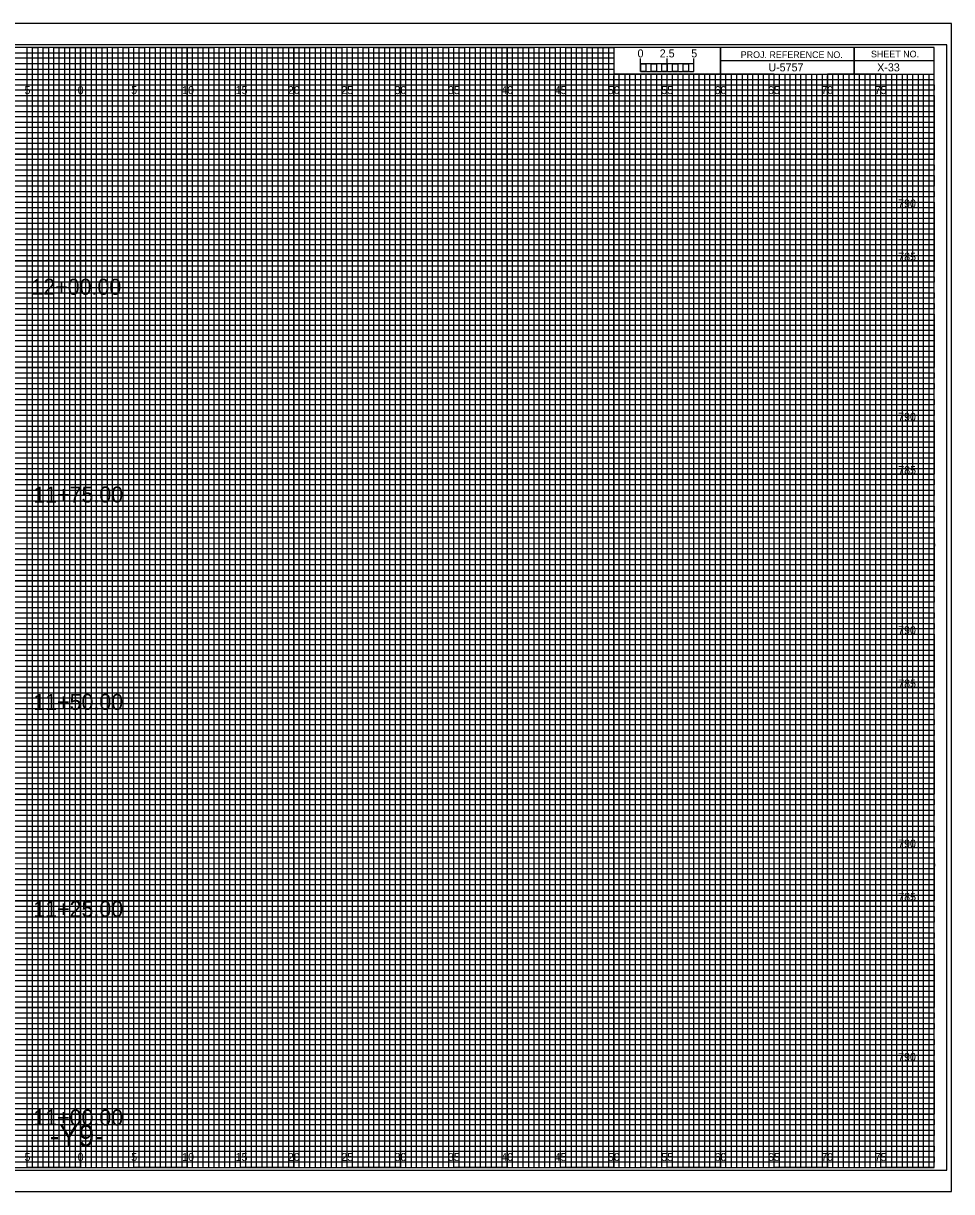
# Model space of a CAD drawing. Extents: x -7 to 162, y 108 to 217.
# Drawn here: x 74.6 to 161.7, y 107.7 to 217.2 of the extents above; entities that cross this region are included whole.
import ezdxf

# ---------------------------------------------------------------- set-up
doc = ezdxf.new("R2010")
doc.units = 0
for name, color, linetype in [('Exist Cross Section Cell', 7, 'Continuous'), ('Exist XS Center Line Elevation Label', 7, 'Continuous'), ('Prop CMT Pvmt Course 2 Wedge', 7, 'Continuous'), ('Prop CMT Pvmt Surface Shoulder', 7, 'Continuous'), ('Prop CMT Shld Paved Course 1', 7, 'Continuous'), ('Prop CMT Shld Paved Course 2', 7, 'Continuous'), ('Prop CMT Shld Paved Course 3', 7, 'Continuous'), ('Prop XS Alignment Label', 7, 'Continuous'), ('Prop XS Bar Scale Labels', 7, 'Continuous'), ('Prop XS Elevation Labels', 7, 'Continuous'), ('Prop XS Hydro Elevations', 7, 'Continuous'), ('Prop XS Project Number', 7, 'Continuous'), ('Prop XS SE Text', 7, 'Continuous'), ('Prop XS Sheet Number', 7, 'Continuous'), ('Prop XS Side Slope Text', 7, 'Continuous'), ('Prop XS Station Labels', 7, 'Continuous'), ('Sheet Cutting Line CELL', 7, 'Continuous')]:
    doc.layers.add(name, color=color, linetype=linetype)

msp = doc.modelspace()

# ---------------------------------------------------------------- linework, layer by layer
at = {"layer": 'Exist Cross Section Cell'}
for p, q in [((75, 215), (70, 215)), ((75, 110), (75, 215)), ((85, 215), (80, 215)), ((80, 215), (80, 110)), ((85, 110), (85, 215)), ((95, 215), (90, 215)), ((90, 215), (90, 110)), ((95, 110), (95, 215)), ((105, 215), (100, 215)), ((100, 215), (100, 110)), ((105, 110), (105, 215)), ((115, 215), (110, 215)), ((110, 215), (110, 110)), ((115, 110), (115, 215)), ((125, 215), (120, 215)), ((120, 215), (120, 110)), ((125, 110), (125, 215)), ((130, 215), (130, 110)), ((135, 110), (135, 212.5)), ((145, 212.5), (140, 212.5)), ((140, 212.5), (140, 110)), ((145, 110), (145, 212.5)), ((155, 212.5), (150, 212.5)), ((150, 212.5), (150, 110)), ((155, 110), (155, 212.5)), ((80, 110), (75, 110)), ((90, 110), (85, 110)), ((100, 110), (95, 110)), ((110, 110), (105, 110)), ((120, 110), (115, 110)), ((130, 110), (125, 110)), ((140, 110), (135, 110)), ((150, 110), (145, 110)), ((160, 110), (155, 110)), ((160, 110), (160, 110))]:
    msp.add_line(p, q, dxfattribs=at)
for points in [[(0, 210), (160, 210), (160, 205), (0, 205)], [(0, 200), (160, 200), (160, 195), (0, 195)], [(0, 190), (160, 190), (160, 185), (0, 185)], [(0, 180), (160, 180), (160, 175), (0, 175)], [(0, 170), (160, 170), (160, 165), (0, 165)], [(0, 160), (160, 160), (160, 155), (0, 155)], [(0, 150), (160, 150), (160, 145), (0, 145)], [(0, 140), (160, 140), (160, 135), (0, 135)], [(0, 130), (160, 130), (160, 125), (0, 125)], [(0, 120), (160, 120), (160, 115), (0, 115)]]:
    msp.add_lwpolyline(points, dxfattribs=at)
at = {"layer": 'Exist XS Center Line Elevation Label'}
for points in [[(72.5, 110), (77.5, 110), (77.5, 215), (82.5, 215), (82.5, 110), (87.5, 110), (87.5, 215), (92.5, 215), (92.5, 110), (97.5, 110), (97.5, 215), (102.5, 215), (102.5, 110), (107.5, 110), (107.5, 215), (112.5, 215), (112.5, 110), (117.5, 110), (117.5, 215), (122.5, 215), (122.5, 110), (127.5, 110), (127.5, 215), (129.97, 215), (130, 215), (130, 212.5), (132.5, 212.5), (132.5, 110), (137.5, 110), (137.5, 212.5), (142.5, 212.5), (142.5, 110), (147.5, 110), (147.5, 212.5), (152.5, 212.5), (152.5, 110), (157.5, 110), (157.5, 212.5)], [(0, 212.5), (137.5, 212.5)], [(0, 202.5), (160, 202.5), (160, 207.5), (0, 207.5)], [(0, 192.5), (160, 192.5), (160, 197.5), (0, 197.5)], [(0, 182.5), (160, 182.5), (160, 187.5), (0, 187.5)], [(0, 172.5), (160, 172.5), (160, 177.5), (0, 177.5)], [(0, 162.5), (160, 162.5), (160, 167.5), (0, 167.5)], [(0, 152.5), (160, 152.5), (160, 157.5), (0, 157.5)], [(0, 142.5), (160, 142.5), (160, 147.5), (0, 147.5)], [(0, 132.5), (160, 132.5), (160, 137.5), (0, 137.5)], [(0, 122.5), (160, 122.5), (160, 127.5), (0, 127.5)], [(0, 112.5), (160, 112.5), (160, 117.5), (0, 117.5)]]:
    msp.add_lwpolyline(points, dxfattribs=at)
at = {"layer": 'Prop CMT Pvmt Course 2 Wedge'}
for p, q in [((75, 110), (75, 215)), ((80, 110), (80, 215)), ((85, 110), (85, 215)), ((90, 110), (90, 215)), ((95, 110), (95, 215)), ((100, 110), (100, 215)), ((105, 110), (105, 215)), ((110, 110), (110, 215)), ((115, 110), (115, 215)), ((120, 110), (120, 215)), ((125, 110), (125, 215)), ((130, 110), (130, 212.34)), ((135, 110), (135, 212.34)), ((140, 110), (140, 212.34)), ((145, 110), (145, 212.34)), ((150, 110), (150, 212.34)), ((155, 110), (155, 212.34)), ((0, 210), (160, 210)), ((0, 205), (160, 205)), ((0, 200), (160, 200)), ((0, 195), (160, 195)), ((0, 190), (160, 190)), ((0, 185), (160, 185)), ((0, 180), (160, 180)), ((0, 175), (160, 175)), ((0, 170), (160, 170)), ((0, 165), (160, 165)), ((0, 160), (160, 160)), ((0, 155), (160, 155)), ((0, 150), (160, 150)), ((0, 145), (160, 145)), ((0, 140), (160, 140)), ((0, 135), (160, 135)), ((0, 130), (160, 130)), ((0, 125), (160, 125)), ((0, 120), (160, 120)), ((0, 115), (160, 115))]:
    msp.add_line(p, q, dxfattribs=at)
at = {"layer": 'Prop CMT Pvmt Surface Shoulder'}
msp.add_lwpolyline([(-5.4, 109.75), (161.2, 109.75), (161.2, 215.25), (-5.4, 215.25)], close=True, dxfattribs=at)
at = {"layer": 'Prop CMT Shld Paved Course 1'}
for p, q in [((133.5, 212.5), (133, 212.5)), ((133, 212.5), (133, 110)), ((133.5, 110), (133.5, 212.5)), ((134.5, 212.5), (134, 212.5)), ((134, 212.5), (134, 110)), ((134.5, 110), (134.5, 212.5)), ((133, 110), (132.5, 110)), ((134, 110), (133.5, 110))]:
    msp.add_line(p, q, dxfattribs=at)
for points in [[(75, 110), (75.5, 110), (75.5, 215), (76, 215), (76, 110)], [(76, 110), (76.5, 110), (76.5, 215), (77, 215), (77, 110)], [(77.5, 110), (78, 110), (78, 215), (78.5, 215), (78.5, 110)], [(78.5, 110), (79, 110), (79, 215), (79.5, 215), (79.5, 110)], [(80, 110), (80.5, 110), (80.5, 215), (81, 215), (81, 110)], [(81, 110), (81.5, 110), (81.5, 215), (82, 215), (82, 110)], [(82.5, 110), (83, 110), (83, 215), (83.5, 215), (83.5, 110)], [(83.5, 110), (84, 110), (84, 215), (84.5, 215), (84.5, 110)], [(85, 110), (85.5, 110), (85.5, 215), (86, 215), (86, 110)], [(86, 110), (86.5, 110), (86.5, 215), (87, 215), (87, 110)], [(87.5, 110), (88, 110), (88, 215), (88.5, 215), (88.5, 110)], [(88.5, 110), (89, 110), (89, 215), (89.5, 215), (89.5, 110)], [(90, 110), (90.5, 110), (90.5, 215), (91, 215), (91, 110)], [(91, 110), (91.5, 110), (91.5, 215), (92, 215), (92, 110)], [(92.5, 110), (93, 110), (93, 215), (93.5, 215), (93.5, 110)], [(93.5, 110), (94, 110), (94, 215), (94.5, 215), (94.5, 110)], [(95, 110), (95.5, 110), (95.5, 215), (96, 215), (96, 110)], [(96, 110), (96.5, 110), (96.5, 215), (97, 215), (97, 110)], [(97.5, 110), (98, 110), (98, 215), (98.5, 215), (98.5, 110)], [(98.5, 110), (99, 110), (99, 215), (99.5, 215), (99.5, 110)], [(100, 110), (100.5, 110), (100.5, 215), (101, 215), (101, 110)], [(101, 110), (101.5, 110), (101.5, 215), (102, 215), (102, 110)], [(102.5, 110), (103, 110), (103, 215), (103.5, 215), (103.5, 110)], [(103.5, 110), (104, 110), (104, 215), (104.5, 215), (104.5, 110)], [(105, 110), (105.5, 110), (105.5, 215), (106, 215), (106, 110)], [(106, 110), (106.5, 110), (106.5, 215), (107, 215), (107, 110)], [(107.5, 110), (108, 110), (108, 215), (108.5, 215), (108.5, 110)], [(108.5, 110), (109, 110), (109, 215), (109.5, 215), (109.5, 110)], [(110, 110), (110.5, 110), (110.5, 215), (111, 215), (111, 110)], [(111, 110), (111.5, 110), (111.5, 215), (112, 215), (112, 110)], [(112.5, 110), (113, 110), (113, 215), (113.5, 215), (113.5, 110)], [(113.5, 110), (114, 110), (114, 215), (114.5, 215), (114.5, 110)], [(115, 110), (115.5, 110), (115.5, 215), (116, 215), (116, 110)], [(116, 110), (116.5, 110), (116.5, 215), (117, 215), (117, 110)], [(117.5, 110), (118, 110), (118, 215), (118.5, 215), (118.5, 110)], [(118.5, 110), (119, 110), (119, 215), (119.5, 215), (119.5, 110)], [(120, 110), (120.5, 110), (120.5, 215), (121, 215), (121, 110)], [(121, 110), (121.5, 110), (121.5, 215), (122, 215), (122, 110)], [(122.5, 110), (123, 110), (123, 215), (123.5, 215), (123.5, 110)], [(123.5, 110), (124, 110), (124, 215), (124.5, 215), (124.5, 110)], [(125, 110), (125.5, 110), (125.5, 215), (126, 215), (126, 110)], [(126, 110), (126.5, 110), (126.5, 215), (127, 215), (127, 110)], [(127.5, 110), (128, 110), (128, 215), (128.5, 215), (128.5, 110)], [(128.5, 110), (129, 110), (129, 215), (129.5, 215), (129.5, 110)], [(130, 110), (130.5, 110), (130.5, 212.5), (131.01, 212.5), (131.01, 110)], [(131, 110), (131.5, 110), (131.5, 212.5), (132, 212.5), (132, 110)], [(135, 110), (135.49, 110), (135.49, 212.5), (136, 212.5), (136, 110)], [(136, 110), (136.5, 110), (136.5, 212.5), (137.03, 212.5), (137.03, 110)], [(137.5, 110), (138, 110), (138, 212.5), (138.5, 212.5), (138.5, 110)], [(138.5, 110), (139, 110), (139, 212.5), (139.5, 212.5), (139.5, 110)], [(140, 110), (140.5, 110), (140.5, 212.5), (141, 212.5), (141, 110)], [(141, 110), (141.5, 110), (141.5, 212.5), (142, 212.5), (142, 110)], [(142.5, 110), (143, 110), (143, 212.5), (143.5, 212.5), (143.5, 110)], [(143.5, 110), (144, 110), (144, 212.5), (144.5, 212.5), (144.5, 110)], [(145, 110), (145.5, 110), (145.5, 212.5), (146, 212.5), (146, 110)], [(146, 110), (146.5, 110), (146.5, 212.5), (147, 212.5), (147, 110)], [(147.5, 110), (148, 110), (148, 212.5), (148.5, 212.5), (148.5, 110)], [(148.5, 110), (149, 110), (149, 212.5), (149.5, 212.5), (149.5, 110)], [(150, 110), (150.5, 110), (150.5, 212.5), (151, 212.5), (151, 110)], [(151, 110), (151.5, 110), (151.5, 212.5), (152, 212.5), (152, 110)], [(152.5, 110), (153, 110), (153, 212.5), (153.5, 212.5), (153.5, 110)], [(153.5, 110), (154, 110), (154, 212.5), (154.5, 212.5), (154.5, 110)], [(155, 110), (155.5, 110), (155.5, 212.5), (156, 212.5), (156, 110)], [(156, 110), (156.5, 110), (156.5, 212.5), (157, 212.5), (157, 110)], [(157.5, 110), (158, 110), (158, 212.5), (158.5, 212.5), (158.5, 110)], [(158.5, 110), (159, 110), (159, 212.5), (159.5, 212.5), (159.5, 110)]]:
    msp.add_lwpolyline(points, dxfattribs=at)
at = {"layer": 'Prop CMT Shld Paved Course 2'}
for p, q in [((132.5, 212.75), (132.5, 213.95)), ((132.5, 213.45), (132.5, 213.95)), ((135, 212.75), (135, 213.95)), ((137.5, 212.75), (137.5, 213.95)), ((137.5, 213.45), (137.5, 213.95))]:
    msp.add_line(p, q, dxfattribs=at)
for points in [[(137.5, 213.45), (132.5, 213.45), (132.5, 212.75), (137.5, 212.75)], [(132.5, 213.45), (133, 213.45), (133, 212.75), (132.5, 212.75)], [(133.5, 213.45), (134, 213.45), (134, 212.75), (133.5, 212.75)], [(134.5, 213.45), (135, 213.45), (135, 212.75), (134.5, 212.75)], [(135.5, 213.45), (136, 213.45), (136, 212.75), (135.5, 212.75)], [(136.5, 213.45), (137, 213.45), (137, 212.75), (136.5, 212.75)]]:
    msp.add_lwpolyline(points, close=True, dxfattribs=at)
at = {"layer": 'Prop CMT Shld Paved Course 3'}
msp.add_lwpolyline([(-6.7, 107.75), (161.65, 107.75), (161.65, 217.25), (-6.7, 217.25)], close=True, dxfattribs=at)
at = {"layer": 'Prop XS Hydro Elevations'}
for p, q in [((152.5, 215), (152.5, 212.5)), ((152.5, 212.5), (152.5, 215)), ((160, 213.75), (140, 213.75)), ((140, 213.75), (140, 212.5)), ((140, 212.5), (160, 212.5))]:
    msp.add_line(p, q, dxfattribs=at)
for points in [[(160, 215), (0, 215), (0, 110), (160, 110)], [(140, 215), (130, 215), (130, 212.52), (140, 212.52)], [(160, 215), (140, 215), (140, 212.5), (160, 212.5)]]:
    msp.add_lwpolyline(points, close=True, dxfattribs=at)
at = {"layer": 'Prop XS Side Slope Text'}
for p, q in [((0, 214.5), (130, 214.5)), ((130, 213.99), (0, 213.99)), ((130, 214.5), (130, 213.99)), ((0, 213.5), (130, 213.5)), ((130, 212.94), (0, 212.94)), ((130, 213.5), (130, 212.94)), ((0, 212), (160, 212))]:
    msp.add_line(p, q, dxfattribs=at)
for points in [[(0, 211.5), (135, 211.5), (160, 211.5), (160, 211), (0, 211)], [(0, 210.5), (160, 210.5), (160, 209.5), (0, 209.5)], [(0, 209), (160, 209), (160, 208.5), (0, 208.49)], [(0, 208), (160, 208), (160, 207), (0, 207)], [(0, 206.5), (160, 206.5), (160, 206), (0, 206)], [(0, 205.5), (160, 205.5), (160, 204.5), (0, 204.5)], [(0, 204), (160, 204), (160, 203.5), (0, 203.5)], [(0, 203), (160, 203), (160, 202), (0, 202)], [(0, 201.5), (160, 201.5), (160, 201), (0, 201)], [(0, 200.5), (160, 200.5), (160, 199.5), (0, 199.5)], [(0, 199), (160, 199), (160, 198.5), (0, 198.5)], [(0, 198), (160, 198), (160, 196.97), (160, 196.5), (160, 196), (0, 196)], [(0, 197), (160, 197), (160, 196.5), (0, 196.5)], [(0, 195.5), (160, 195.5), (160, 194.5), (0, 194.52)], [(0, 194.52), (160, 194.5), (160, 194), (0, 194)], [(0, 193.5), (160, 193.5), (160, 193), (0, 193)], [(0, 192), (160, 192), (160, 191.5), (0, 191.5)], [(0, 191), (160, 191), (160, 190.5), (0, 190.5)], [(-0.04, 189.44), (160, 189.44), (160, 188.94), (-0.04, 188.94)], [(0, 188.5), (160, 188.5), (160, 188), (0, 188)], [(0, 187), (160, 187), (160, 186.5), (0, 186.5)], [(0, 186), (160, 186), (160, 185.5), (0, 185.5)], [(0, 184.5), (160, 184.5), (160, 184), (0, 184)], [(0, 183.5), (160, 183.5), (160, 183), (0, 183)], [(0, 182), (160, 182), (160, 181.5), (0, 181.5)], [(0, 181), (160, 181), (160, 180.5), (0, 180.5)], [(0, 179.5), (160, 179.5), (160, 178.99), (0, 179)], [(0, 178.5), (160, 178.5), (160, 178), (0, 178)], [(0, 177), (160, 177), (160, 176.5), (0, 176.5)], [(0, 176), (160, 176), (160, 175.5), (0, 175.5)], [(0, 174.5), (160, 174.5), (160, 174), (0, 174)], [(0, 173.5), (160, 173.5), (160, 173), (0, 173)], [(0, 172), (160, 172), (160, 171.5), (0, 171.5)], [(0, 171), (160, 171), (160, 170.5), (0, 170.5)], [(0, 169.5), (160, 169.5), (160, 169), (0, 169)], [(0, 168.5), (160.03, 168.46), (160, 168), (0, 168)], [(0, 167), (160, 167), (160, 166.5), (0, 166.5)], [(0, 166), (160, 166), (160, 165.5), (0, 165.5)], [(0, 164.5), (160, 164.5), (160, 164), (0, 164)], [(0, 163.5), (160, 163.5), (160, 163), (0, 163)], [(0, 162), (160, 162), (160, 161.5), (0, 161.5)], [(0, 161), (160, 161), (160, 160.5), (0, 160.5)], [(0, 159.5), (160, 159.5), (160, 159), (0, 159)], [(0, 158.5), (160, 158.5), (160, 158), (0, 158)], [(0, 157), (160, 157), (160, 156.5), (0, 156.5)], [(0, 156), (160, 156), (160, 155.5), (0, 155.5)], [(0, 154.5), (160, 154.5), (160, 154), (0, 154)], [(0, 153.5), (160, 153.5), (160, 153), (0, 153)], [(0, 152), (160, 152), (160, 151.5), (0, 151.5)], [(0, 151), (160, 151), (160, 150.5), (0, 150.5)], [(0, 149.5), (160, 149.5), (160, 148.99), (0, 149)], [(0, 148.5), (160, 148.5), (160, 148), (0, 148)], [(0, 147), (160, 147), (160, 146.5), (0, 146.5)], [(0, 146), (160, 146), (160, 145.5), (0, 145.5)], [(0, 144.5), (160, 144.5), (160, 144), (0, 144)], [(0, 143.5), (160, 143.5), (160, 143), (0, 143)], [(0, 142), (160, 142), (160, 141.5), (0, 141.5)], [(0, 141), (160, 141), (160, 140.5), (0, 140.5)], [(0, 139.5), (160, 139.5), (160, 139), (0, 139)], [(0, 138.5), (160.03, 138.46), (160, 138), (0, 138)], [(0, 137), (160, 137), (160, 136.5), (0, 136.5)], [(0, 136), (160, 136), (160, 135.5), (0, 135.5)], [(0, 134.5), (160, 134.5), (160, 134), (0, 134)], [(0, 133.5), (160, 133.5), (160, 133), (0, 133)], [(0, 132), (160, 132), (160, 131.5), (0, 131.5)], [(0, 131), (160, 131), (160, 130.5), (0, 130.5)], [(0, 129.5), (160, 129.5), (160, 129), (0, 129)], [(0, 128.5), (160, 128.5), (160, 128), (0, 128)], [(0, 127), (160, 127), (160, 126.5), (0, 126.5)], [(0, 126), (160, 126), (160, 125.5), (0, 125.5)], [(0, 124.5), (160, 124.5), (160, 124), (0, 124)], [(0, 123.5), (160, 123.5), (160, 123), (0, 123)], [(0, 122), (160, 122), (160, 121.5), (0, 121.5)], [(0, 121), (160, 121), (160, 120.5), (0, 120.5)], [(0, 119.5), (160, 119.5), (160, 119), (0, 119)], [(0, 118.5), (160, 118.5), (160, 118), (0, 118)], [(0, 117), (160, 117), (160, 116.5), (0, 116.5)], [(0, 116), (160, 116), (160, 115.5), (0, 115.5)], [(0, 114.5), (160, 114.5), (160, 114), (0, 114)], [(0, 113.5), (160, 113.5), (160, 113), (0, 113)], [(0, 112), (160, 112), (160, 111.5), (0, 111.5)], [(0, 111), (160, 111), (160, 110.5), (0, 110.5)]]:
    msp.add_lwpolyline(points, dxfattribs=at)
at = {"layer": 'Sheet Cutting Line CELL'}
for p, q in [((161.65, 217.25), (-6.7, 217.25)), ((-6.7, 107.75), (161.65, 107.75))]:
    msp.add_line(p, q, dxfattribs=at)

# ---------------------------------------------------------------- texts
at = {"layer": 'Prop CMT Shld Paved Course 2'}
msp.add_text('0', height=0.75, dxfattribs=at).set_placement((132.21, 214.06))
at = {"layer": 'Prop XS Alignment Label'}
msp.add_text('-Y9-', height=2, dxfattribs=at).set_placement((77.12, 112))
at = {"layer": 'Prop XS Bar Scale Labels'}
for s, p in [('2.5', (134.29, 214.06)), ('5', (137.24, 214.06))]:
    msp.add_text(s, height=0.75, dxfattribs=at).set_placement(p)
at = {"layer": 'Prop XS Elevation Labels'}
for s, p in [('790', (156.63, 200)), ('785', (156.64, 195)), ('790', (156.63, 180)), ('785', (156.64, 175)), ('790', (156.63, 160)), ('785', (156.64, 155)), ('790', (156.63, 140)), ('785', (156.64, 135)), ('790', (156.63, 120))]:
    msp.add_text(s, height=0.75, dxfattribs=at).set_placement(p)
at = {"layer": 'Prop XS Hydro Elevations'}
for s, p in [('PROJ. REFERENCE NO.', (141.88, 214)), ('SHEET NO.', (154.09, 214.06))]:
    msp.add_text(s, height=0.625, dxfattribs=at).set_placement(p)
at = {"layer": 'Prop XS Project Number'}
msp.add_text('U-5757', height=0.75, dxfattribs=at).set_placement((144.47, 212.75))
at = {"layer": 'Prop XS SE Text'}
for s, p in [('5', (74.74, 210.62)), ('0', (79.73, 210.62)), ('0', (79.73, 210.62)), ('5', (84.74, 210.62)), ('10', (89.52, 210.62)), ('15', (94.53, 210.62)), ('20', (99.43, 210.62)), ('25', (104.44, 210.62)), ('30', (109.43, 210.62)), ('35', (114.44, 210.62)), ('40', (119.43, 210.62)), ('45', (124.44, 210.62)), ('50', (129.43, 210.62)), ('55', (134.44, 210.62)), ('60', (139.43, 210.62)), ('65', (144.44, 210.62)), ('70', (149.43, 210.62)), ('75', (154.44, 210.62)), ('5', (74.74, 110.62)), ('0', (79.73, 110.62)), ('0', (79.73, 110.62)), ('5', (84.74, 110.62)), ('10', (89.52, 110.62)), ('15', (94.53, 110.62)), ('20', (99.43, 110.62)), ('25', (104.44, 110.62)), ('30', (109.43, 110.62)), ('35', (114.44, 110.62)), ('40', (119.43, 110.62)), ('45', (124.44, 110.62)), ('50', (129.43, 110.62)), ('55', (134.44, 110.62)), ('60', (139.43, 110.62)), ('65', (144.44, 110.62)), ('70', (149.43, 110.62)), ('75', (154.44, 110.62))]:
    msp.add_text(s, height=0.75, dxfattribs=at).set_placement(p)
at = {"layer": 'Prop XS Sheet Number'}
msp.add_text('X-33', height=0.75, dxfattribs=at).set_placement((154.67, 212.75))
at = {"layer": 'Prop XS Station Labels'}
for s, p in [('12+00.00', (75.39, 191.81)), ('11+75.00', (75.57, 172.34)), ('11+50.00', (75.57, 152.9)), ('11+25.00', (75.57, 133.5)), ('11+00.00', (75.57, 113.95))]:
    msp.add_text(s, height=1.5, dxfattribs=at).set_placement(p)

doc.saveas('drawing.dxf')
